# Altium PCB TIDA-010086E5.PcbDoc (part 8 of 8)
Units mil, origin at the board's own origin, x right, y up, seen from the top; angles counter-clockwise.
Board outline 6400 x 6200 mil, 6 copper layers (Top Layer, Power, AGND, Signal, PGND, Bottom Layer), stack 70.536 mil thick; 717 components, 376 nets, 2259 pads, 2183 vias.
Unrouted connection lines stored in the file: 1424.
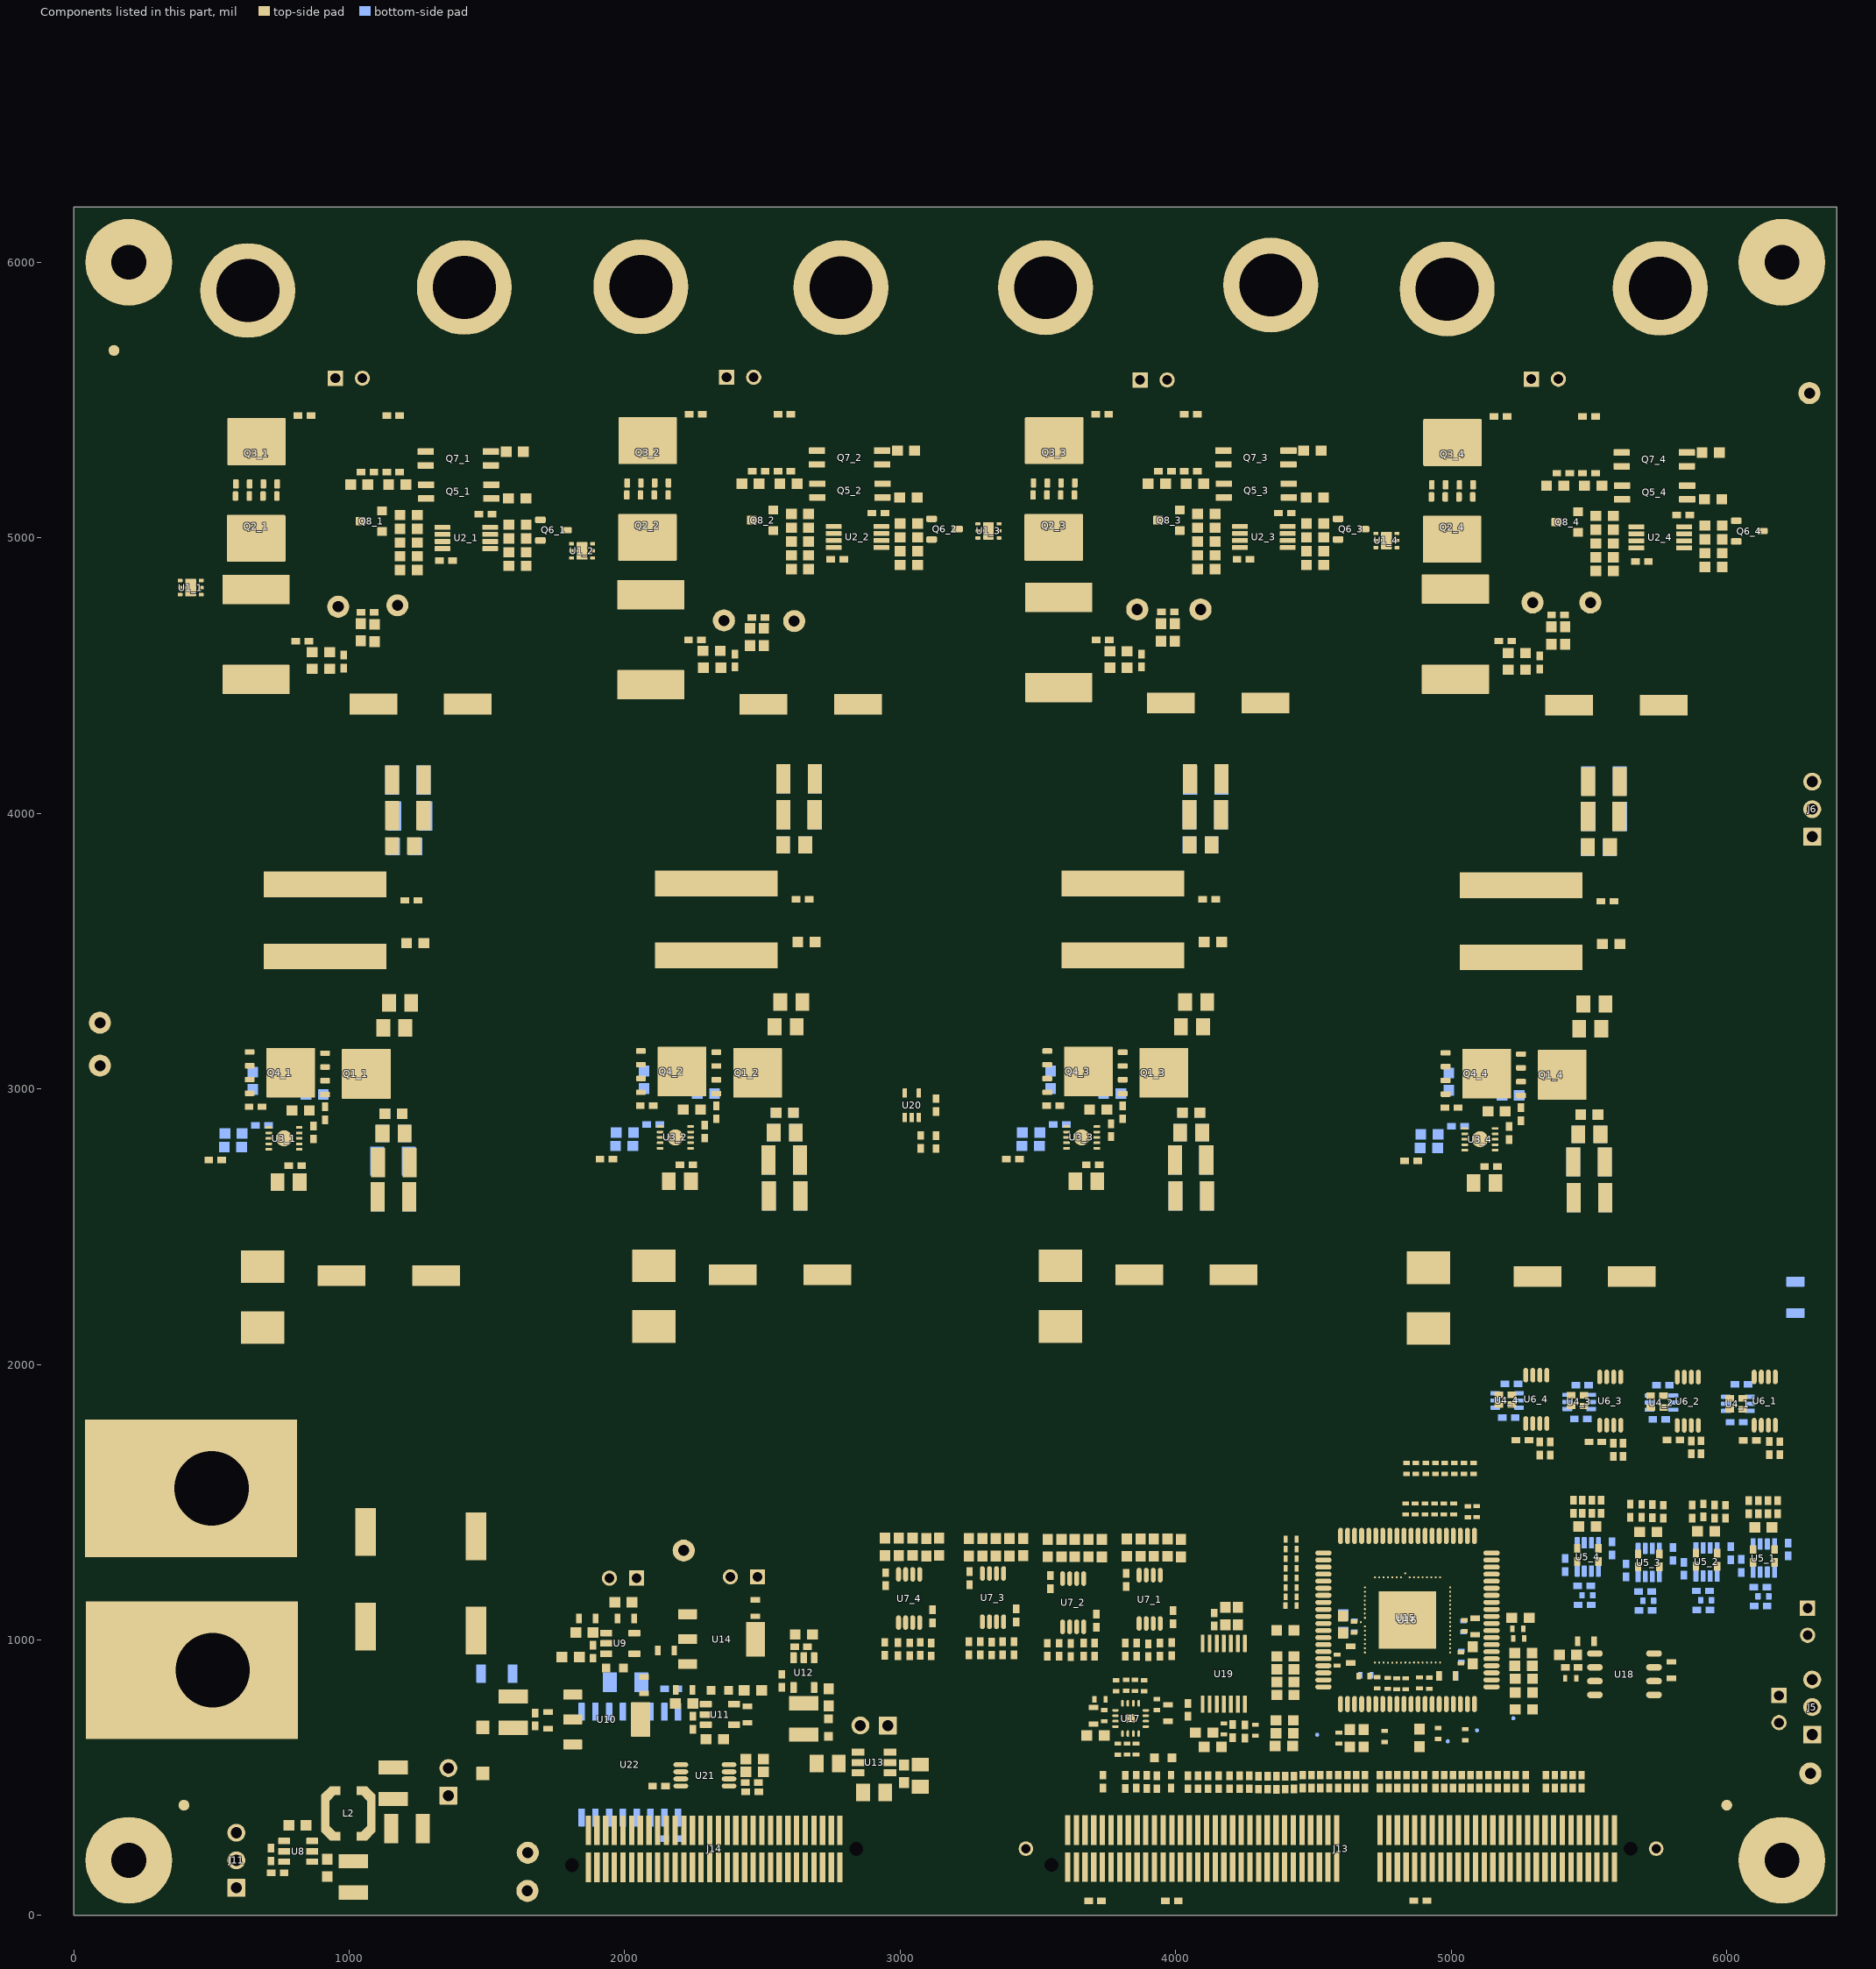
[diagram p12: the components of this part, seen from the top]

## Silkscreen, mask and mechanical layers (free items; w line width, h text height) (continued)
M10 Fab Notes:
  drawing of 189 lines, arcs and shapes, not listed
  text "DESIGN INFORMATION" at 16452.02,6511.32 h60
  text "MIN. TRACK WIDTH:" at 15807.46,6379.19 h60
  text "6" at 16903.7,6379.2 h60
  text "MIL" at 17058.46,6379.19 h60
  text "7.874" at 16737.32,6257.51 h60
  text "MIN. CLEARANCE:" at 15807.46,6255.07 h60
  text "MIL" at 17058.46,6255.07 h60
  text "MIN. VIA PAD SIZE:" at 15807.46,6130.94 h60
  text "20" at 16873.71,6130.94 h60
  text "MIL" at 17058.46,6130.94 h60
  text "0.15mm (5.9MIL)" at 16502.46,6001.04 h60
  text "MINIMUM ANNULAR RING" at 15478.23,5992.82 h60
  text "EXTERNAL" at 17210.46,5992.82 h60
  text "PER" at 15678.23,5882.69 h60
  text "IPC-D-275 CLASS 2 LEVEL C" at 15898.23,5882.69 h60
  text "MIL, HOLES" at 17386.46,5782.21 h60
  text "+/-" at 16994,5773.63 h60
  text "+/-" at 17848,5773.63 h60
  text "REGISTRATION TOLERANCES:" at 15478.23,5772.56 h60
  text "METAL" at 16678,5772.56 h60
  text "5" at 17254.2,5772.57 h60
  text "3" at 18087.2,5772.57 h60
  text "MIL" at 18203.46,5772.56 h60
  text "HOLE SIZE TOLERANCE (UNLESS OTHERWISE SPECIFIED):" at 15478.23,5674.25 h60
  text "+/-" at 17848,5671.38 h60
  text "3" at 18087.2,5670.31 h60
  text "MIL" at 18203.46,5670.31 h60
  text "MATERIAL:" at 15403.46,5532.66 h60
  text "FR-4 High Tg" at 16389.9,5404.14 h60
  text "X" at 16244.46,5395.69 h60
  text "FR-408" at 15824.46,5391.63 h60
  text "OTHER" at 17312.46,5391.63 h60
  text "X" at 18233.45,5277.07 h60
  text "X" at 16013.46,5248.69 h60
  text "62 MIL (1.6mm) +/-10%" at 16144.56,5248.6 h60
  text "THICKNESS:" at 15478.23,5240.38 h60
  text "OTHER" at 17429.46,5240.38 h60
  text "TOLERANCE:" at 15478.23,5102.07 h60
  text "ANSI IPC-6012 TYPE 3 CLASS 2" at 16504.48,5102.07 h60
  text "OTHER +/-" at 16504.46,4957.88 h60
  text "BOW & TWIST:" at 15478.23,4812.69 h60
  text "X" at 16326.46,4812.69 h60
  text "ANSI IPC-6012 TYPE 3 CLASS 2" at 16504.48,4812.69 h60
  text "OTHER +/-" at 16504.46,4665.99 h60
  text "DRILLING:" at 15403.46,4535.37 h60
  text "X" at 16138.46,4429.69 h60
  text "NC_DRILL FILES" at 17164.46,4430.18 h60
  text "REFERENCE:" at 15478.23,4426.25 h60
  text "AS SHOWN" at 16313.46,4426.25 h60
  text "OTHER" at 17462.46,4284 h60
  text "X" at 16616.46,4282.69 h60
  text "PTH COPPER THICKNESS:" at 15477.91,4280.47 h60
  text "20-30 um" at 16745.14,4280.47 h60
  text "BOARD FINISH:" at 15403.46,4132.87 h60
  text "X" at 17023.46,4025.69 h60
  text "SILKSCREEN:" at 15558.68,4022.74 h60
  text "TOP" at 16633.46,4022.74 h60
  text "BOTTOM" at 17144.46,4022.74 h60
  text "X" at 16513.46,4016.69 h60
  text "SILKSCREEN COLOR:" at 15558.68,3867.55 h60
  text "WHITE" at 16633.46,3867.55 h60
  text "OTHER" at 17144.46,3867.55 h60
  text "X" at 16510.46,3866.69 h60
  text "X" at 16645.46,3728.69 h60
  text "GREEN" at 16764.46,3724.11 h60
  text "OTHER" at 17382.46,3724.11 h60
  text "SOLDER RESIST COLOR:" at 15558.68,3717.24 h60
  text "MATTE" at 16764.46,3569.85 h60
  text "SEMI-GLOSS" at 17382,3569.22 h60
  text "IMMERSION GOLD (ENIG)" at 16464.46,3397.08 h60
  text "X" at 16276.46,3390.69 h60
  text "ENEPIG" at 17802,3389.86 h60
  text "SURFACE FINISH:" at 15403.46,3388.86 h60
  text "IMM. TIN/SILVER OR EQUIV" at 15733,3251.55 h60
  text "OTHER" at 17164.46,3247.61 h60
  text "ARRAY/PANEL:" at 15403.46,3092.23 h60
  text "CUT AND TRIM PER M1 BOARD OUTLINE" at 16464.46,3084.01 h60
  text "N.C. ROUTE" at 16464.46,2948.04 h60
  text "V. SCORE" at 17330.46,2948.04 h60
  text "CERTIFICATION:" at 15403.46,2818.92 h60
  text "MATERIALS AND WORKMANSHIP FOR ALL PCBS" at 16128.46,2818.92 h60
  text "TO MEET OR EXCEED THE REQUIREMENTS OF:" at 16128.46,2724.85 h60
  text "ANSI IPC-A-600F CLASS ->" at 15893.96,2596.22 h60
  text "2" at 17651.96,2596.22 h60
  text "1" at 17336.96,2594.73 h60
  text "3" at 18005.96,2594.73 h60
  text "X" at 17533.46,2593.69 h60
  text "X" at 15753.46,2587.69 h60
  text "RoHS" at 16705.96,2448.54 h60
  text "OTHER" at 17350.36,2448.54 h60
  text "PER ORDER" at 17747.42,2448.54 h60
  text "ALL BOARDS MUST MEET OR EXCEED UL94-V0 REQUIREMENTS." at 15431,2294.71 h60
  text "PCB MUST BEAR THE UL94V-0 UL REGISTERED MATERIAL ID NUMBER" at 15430,2200 h60
  text "ADDITIONAL REQUIREMENTS:" at 15420,2040 h60
  text "YES" at 16240,1930 h60
  text "MICROSECTION:" at 15440,1915 h60
  text "REQUIRED" at 17197.46,1790.39 h60
  text "NONE" at 16735.96,1787.53 h60
  text "X" at 17078.46,1788.31 h60
  text "PER ORDER" at 17789.46,1787.53 h60
  text "BARE BOARD ELEC. TEST:" at 15440,1775 h60
  text "XX MIL VIAS REQUIRE NON-CONDUCTIVE FILL AND PLANARIZE" at 15595,1550 h59
  text "12.5mil MIL VIAS REQUIRE CONDUCTIVE FILL AND PLANARIZE" at 15595,1480 h60
  text "X" at 15471.31,1464 h60
  text "OUTER XX MIL TRACES REQUIRE 50 OHM SINGLE-ENDED IMPEDANCE" at 15595,1340 h58
  text "LAYER 2 & 3 (INNER LAYERS) XX MIL WIDE, XX MIL SPACE / TRACES REQUIRE 100 OHM DIFFERENTIAL IMPEDANCE" at 15585,1095 h60
  text ".Layer_Name" at 577,-858.49 h60
M11 Gerber Information:
  lines w10: -292,-930.17 6308,-930.17 ; -292,-726.83 6310,-726.83 ; -292,-523.5 -292,-1133.5 3713,-1133.5 6310,-1133.5 6310,-523.5 -291.5,-523.5 -291.5,-1133.5 ; 3440,-726.83 3440,-523.5 ; 4280,-726.83 4280,-523.5 ; 4902,-1140 4902,-937.17
  text "ALL ARTWORK VIEWED FROM TOP SIDE" at -228.5,-655.67 h60
  text "BOARD #:" at 2248,-655.67 h60
  text ".PRJ_Number" at 2793.5,-655.67 h60
  text "REV:" at 3638,-655.67 h60
  text ".PCB_Rev" at 3929.5,-655.67 h60
  text "SVN REV:" at 4476,-655.67 h60
  text ".VersionControl_RevNumber" at 4982,-655.67 h60
  text "TID #:" at 2248,-859 h60
  text ".TID" at 2793.5,-859 h60
  text "LAYER NAME =" at -214.65,-864.49 h60
  text ".plot_File_Name" at 577,-1064.34 h60
  text "GENERATED    :" at 2250,-1064.34 h60
  text ".Print_Date" at 3119.5,-1064.34 h60
  text ".Print_Time" at 3848.5,-1064.34 h60
  text "TEXAS INSTRUMENTS" at 5113,-1064.34 h60
  text "PLOT NAME =" at -214.65,-1070.34 h60
M12 Stackup:
  drawing of 503 lines, arcs and shapes, not listed
  text "Layer" at 9821.59,7874.94 h60
  text "Name" at 10231.51,7874.94 h60
  text "Material" at 11561.12,7874.94 h60
  text "Thickness" at 12160.97,7874.94 h60
  text "Constant" at 12810.81,7874.94 h60
  text "Board Layer Stack" at 13380.67,7874.94 h60
  text "Top Overlay" at 10231.51,7754.94 h60
  text "Top Solder" at 10231.51,7634.94 h60
  text "SM-001" at 11561.12,7634.94 h60
  text "1.00mil" at 12160.97,7634.94 h60
  text "4" at 12810.81,7634.94 h60
  text "Top Surface Finish" at 10231.51,7514.94 h60
  text "PbSn" at 11561.12,7514.94 h60
  text "0.79mil" at 12160.97,7514.94 h60
  text "1" at 9821.59,7394.94 h60
  text "Top Layer" at 10231.51,7394.94 h60
  text "CF-005" at 11561.12,7394.94 h60
  text "2.76mil" at 12160.97,7394.94 h60
  text "Dielectric 6" at 10231.51,7274.94 h60
  text "PP-006" at 11561.12,7274.94 h60
  text "2.80mil" at 12160.97,7274.94 h60
  text "4.1" at 12810.81,7274.94 h60
  text "Dielectric 1" at 10231.51,7154.94 h60
  text "PP-017" at 11561.12,7154.94 h60
  text "5.10mil" at 12160.97,7154.94 h60
  text "4.3" at 12810.81,7154.94 h60
  text "2" at 9821.59,7034.94 h60
  text "Power" at 10231.51,7034.94 h60
  text "CF-005" at 11561.12,7034.94 h60
  text "2.76mil" at 12160.97,7034.94 h60
  text "Dielectric 4" at 10231.51,6914.94 h60
  text "PP-017" at 11561.12,6914.94 h60
  text "5.10mil" at 12160.97,6914.94 h60
  text "4.3" at 12810.81,6914.94 h60
  text "3" at 9821.59,6794.94 h60
  text "AGND" at 10231.51,6794.94 h60
  text "CF-005" at 11561.12,6794.94 h60
  text "2.76mil" at 12160.97,6794.94 h60
  text "Dielectric 2" at 10231.51,6674.94 h60
  text "Core-039" at 11561.12,6674.94 h60
  text "28.00mil" at 12160.97,6674.94 h60
  text "4.8" at 12810.81,6674.94 h60
  text "4" at 9821.59,6554.94 h60
  text "Signal" at 10231.51,6554.94 h60
  text "CF-005" at 11561.12,6554.94 h60
  text "2.76mil" at 12160.97,6554.94 h60
  text "Dielectric 5" at 10231.51,6434.94 h60
  text "PP-017" at 11561.12,6434.94 h60
  text "5.10mil" at 12160.97,6434.94 h60
  text "4.3" at 12810.81,6434.94 h60
  text "5" at 9821.59,6314.94 h60
  text "PGND" at 10231.51,6314.94 h60
  text "CF-005" at 11561.12,6314.94 h60
  text "2.76mil" at 12160.97,6314.94 h60
  text "Dielectric 3" at 10231.51,6194.94 h60
  text "PP-017" at 11561.12,6194.94 h60
  text "5.10mil" at 12160.97,6194.94 h60
  text "4.3" at 12810.81,6194.94 h60
  text "Dielectric 7" at 10231.51,6074.94 h60
  text "PP-006" at 11561.12,6074.94 h60
  text "2.80mil" at 12160.97,6074.94 h60
  text "4.1" at 12810.81,6074.94 h60
  text "6" at 9821.59,5954.94 h60
  text "Bottom Layer" at 10231.51,5954.94 h60
  text "CF-005" at 11561.12,5954.94 h60
  text "2.76mil" at 12160.97,5954.94 h60
  text "Bottom Surface Finish" at 10231.51,5834.94 h60
  text "PbSn" at 11561.12,5834.94 h60
  text "0.79mil" at 12160.97,5834.94 h60
  text "Bottom Solder" at 10231.51,5714.94 h60
  text "SM-001" at 11561.12,5714.94 h60
  text "1.00mil" at 12160.97,5714.94 h60
  text "4" at 12810.81,5714.94 h60
  text "Bottom Overlay" at 10231.51,5594.94 h60
  text ".Layer_Name" at 582.81,-853.69 h60
M13 Component Bodies Top:
  text ".Layer_Name" at 577,-858.49 h60
M14 Component Bodies Bottom:
  text ".Layer_Name" at 577,-858.49 h60
M15 Courtyards Top:
  text ".Layer_Name" at 577,-858.49 h60
M16 Courtyards Bottom:
  text ".Layer_Name" at 577,-858.49 h60
Drill Drawing:
  text ".Layer_Name" at 582.81,-853.69 h60
M17 Embedded Cavity:
  text ".Layer_Name" at 577,-858.49 h60
M18 Embedded Assembly:
  text ".Layer_Name" at 577,-858.49 h60
M19 Embedded Keepout:
  text ".Layer_Name" at 577,-858.49 h60

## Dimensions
0,0 to 0,6200 on M2 Board Dimensions
0,0 to 6400,0 on M2 Board Dimensions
